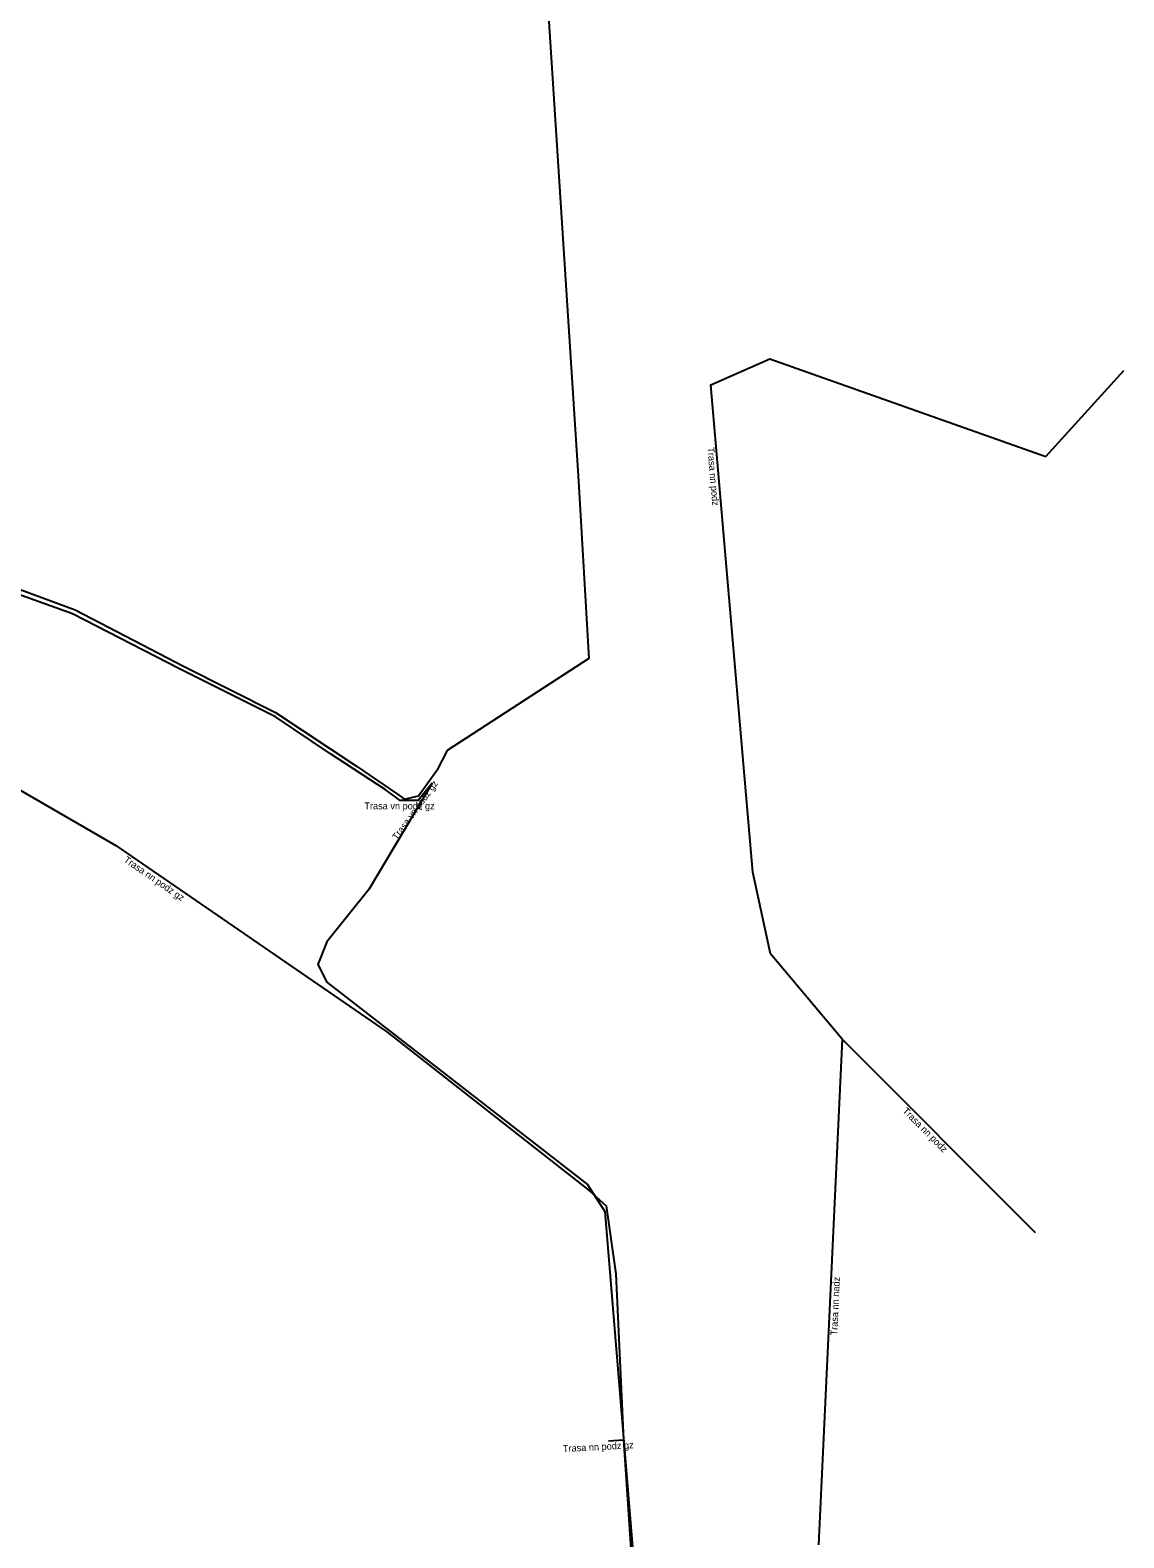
# Model space of a CAD drawing. Extents: x -725057 to -724754, y -1049160 to -1048651.
# Drawn here: x -724977.7 to -724897.9, y -1048930.9 to -1048820.9 of the extents above; entities that cross this region are included whole.
import ezdxf

# ---------------------------------------------------------------- set-up
doc = ezdxf.new("R2010")
doc.units = 0
for name, color, linetype in [('Popiskový text - Ostatní atributy Trasy', 7, 'Continuous'), ('Spojnice NN', 7, 'Continuous'), ('Spojnice VN', 7, 'Continuous')]:
    doc.layers.add(name, color=color, linetype=linetype)

msp = doc.modelspace()

# ---------------------------------------------------------------- linework, layer by layer
at = {"layer": 'Spojnice NN'}
for points in [[(-724918.48, -1048894.51), (-724923.7, -1048888.28), (-724925, -1048882.32), (-724928.05, -1048846.79), (-724923.75, -1048844.91), (-724903.63, -1048852.02), (-724897.94, -1048845.74)], [(-725019.85, -1048864.07), (-725000.49, -1048868.1), (-724989.28, -1048871.33), (-724988.91, -1048871.4), (-724985.03, -1048872.54), (-724971.44, -1048880.39), (-724951.69, -1048893.97), (-724936.92, -1048905.54), (-724935.69, -1048906.65), (-724934.98, -1048911.62), (-724934.42, -1048923.73)], [(-724918.48, -1048894.51), (-724920.2, -1048931.38)], [(-724918.48, -1048894.51), (-724904.4, -1048908.61)], [(-724935.53, -1048923.79), (-724934.42, -1048923.73)], [(-724934.42, -1048923.73), (-724931.11, -1048972.86)]]:
    msp.add_lwpolyline(points, dxfattribs=at)
at = {"layer": 'Spojnice VN'}
for points in [[(-724941.12, -1048801.09), (-724937.71, -1048853.82), (-724936.94, -1048866.74), (-724947.29, -1048873.46), (-724948, -1048874.87)], [(-725054.17, -1048856.55), (-725057.44, -1048853.35), (-725055.49, -1048850.01), (-725056, -1048848.07), (-725054.97, -1048842.15), (-725053.27, -1048841.1), (-725050.1, -1048841), (-725039.2, -1048843.4), (-725029.3, -1048845.4), (-725024.2, -1048846.4), (-725015.5, -1048848.9), (-725009.5, -1048852.6), (-725005.9, -1048853.5), (-724998.8, -1048855.3), (-724989, -1048858.1), (-724982, -1048860.4), (-724974.4, -1048863.2), (-724966.5, -1048867.3), (-724959.8, -1048870.7), (-724953.9, -1048874.6), (-724950.91, -1048876.65)], [(-724951, -1048876.88), (-724951.8, -1048876.3), (-724955.8, -1048873.7), (-724959.8, -1048871), (-724966.8, -1048867.5), (-724974.6, -1048863.5), (-724985.7, -1048859.5), (-724995.7, -1048856.6), (-725009.8, -1048852.8), (-725015.5, -1048849.2), (-725024.4, -1048846.7), (-725029.2, -1048845.7), (-725036.9, -1048844.1), (-725050, -1048841.4), (-725053.2, -1048841.3), (-725054.06, -1048842.26), (-725055.02, -1048848.37), (-725056.44, -1048853.55), (-725054.17, -1048856.55)], [(-724950.91, -1048876.65), (-724950.4, -1048877), (-724949.37, -1048876.76), (-724948, -1048874.87)], [(-724948.38, -1048875.85), (-724953, -1048883.6), (-724956.06, -1048887.41), (-724956.72, -1048889.07), (-724956.05, -1048890.35), (-724937.04, -1048905.1), (-724935.78, -1048907.08), (-724933.51, -1048934.79), (-724931.99, -1048958.28), (-724929.58, -1048991.23), (-724928.45, -1049009.35), (-724927.82, -1049010.29), (-724922.87, -1049013.13), (-724922.05, -1049014.45), (-724920.15, -1049051.91), (-724918.93, -1049078.06), (-724917.41, -1049089.83), (-724917.12, -1049112.39), (-724916.32, -1049116.09), (-724915.71, -1049122.92), (-724916.11, -1049125.96), (-724915.65, -1049129.84)], [(-724948.38, -1048875.85), (-724949.4, -1048877.1), (-724950.7, -1048877.1), (-724951, -1048876.88)]]:
    msp.add_lwpolyline(points, dxfattribs=at)

# ---------------------------------------------------------------- texts
at = {"layer": 'Popiskový text - Ostatní atributy Trasy'}
for s, rotation, p in [('Trasa nn podz', 274.9064, (-724928.31, -1048851.37)), ('Trasa vn podz gz', 54.0629, (-724950.93, -1048880.03)), ('Trasa nn podz gz', 325.4878, (-724970.91, -1048881.54)), ('Trasa nn podz', 314.9654, (-724914.12, -1048899.79)), ('Trasa nn nadz', 87.3307, (-724918.84, -1048916.12)), ('Trasa nn podz gz', 3.0941, (-724938.83, -1048924.62))]:
    msp.add_text(s, height=0.5, rotation=rotation, dxfattribs=at).set_placement(p)
msp.add_text('Trasa vn podz gz', height=0.5, dxfattribs=at).set_placement((-724953.32, -1048877.75))

doc.saveas('drawing.dxf')
